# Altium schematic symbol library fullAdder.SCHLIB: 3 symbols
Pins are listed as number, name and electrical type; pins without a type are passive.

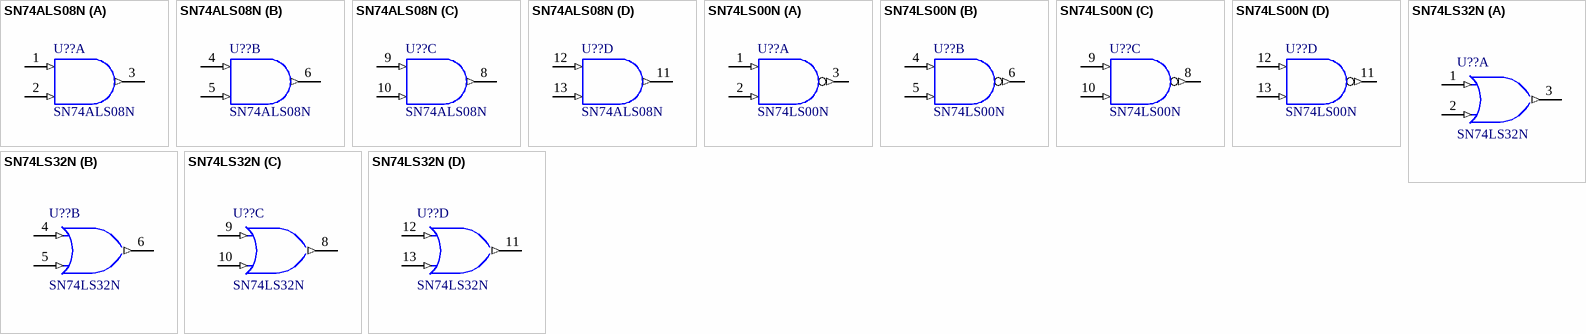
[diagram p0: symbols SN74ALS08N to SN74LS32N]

## SN74ALS08N
designator U??
Quadruple 2-Input Positive-AND Gate; Manufacturer: Texas Instruments; Class I: Logic
footprint DIP-14/D19.7
signal-integrity model SN74ALS08N
pins on every part: 7 GND (power) hidden to GND, 14 VCC (power) hidden to VCC
part A pins: 1 A (in), 2 B (in), 3 Y (out)
part B pins: 4 A (in), 5 B (in), 6 Y (out)
part C pins: 8 Y (out), 9 A (in), 10 B (in)
part D pins: 11 Y (out), 12 A (in), 13 B (in)

## SN74LS00N
designator U??
Quadruple 2-Input Positive-NAND Gate; Manufacturer: Texas Instruments; Class I: Logic
footprint DIP-14/D19.7
simulation model SN74LS00 (SIMCODE)
signal-integrity model SN74LS00N
pins on every part: 7 GND (power) hidden to GND, 14 VCC (power) hidden to VCC
part A pins: 1 A (in), 2 B (in), 3 Y (out)
part B pins: 4 A (in), 5 B (in), 6 Y (out)
part C pins: 8 Y (out), 9 A (in), 10 B (in)
part D pins: 11 Y (out), 12 A (in), 13 B (in)

## SN74LS32N
designator U??
Quadruple 2-Input Positive-OR Gate; Manufacturer: Texas Instruments; Class I: Logic
footprint DIP-14/D19.7
simulation model SN74LS32 (SIMCODE)
signal-integrity model SN74LS32N
pins on every part: 7 GND (power) hidden to GND, 14 VCC (power) hidden to VCC
part A pins: 1 A (in), 2 B (in), 3 Y (out)
part B pins: 4 A (in), 5 B (in), 6 Y (out)
part C pins: 8 Y (out), 9 A (in), 10 B (in)
part D pins: 11 Y (out), 12 A (in), 13 B (in)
